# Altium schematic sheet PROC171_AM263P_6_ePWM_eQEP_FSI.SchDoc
size 431 x 279 mm; Date: Not shown in title block; ApprovedBy: Not shown in title block; CheckedBy: Not shown in title block; Author: Not shown in title block; CompanyName: Not shown in title block; Engineer: Not shown in title block; Organization: Not shown in title block; Address1: Not shown in title block; Address2: Not shown in title block; Address3: Not shown in title block; Address4: Not shown in title block; DocumentNumber: 10; Revision: Use project parameter SCH_Rev; SheetNumber: 10; SheetTotal: 26; PageSetup: Record=PageOptions¦CenterHorizontal=True¦CenterVertical=True¦PrintScale=1.00¦XCorrection=1.00¦YCorrection=1.00¦PrintKind=0¦BorderSize=5000000¦LeftOffset=0¦BottomOffset=0¦Orientation=2¦PaperLength=1000¦PaperWidth=1000¦Scale=100¦PaperSource=15¦PrintQuality=600¦MediaType=1¦DitherType=10¦PaperKind=Letter¦PrintScaleMode=1
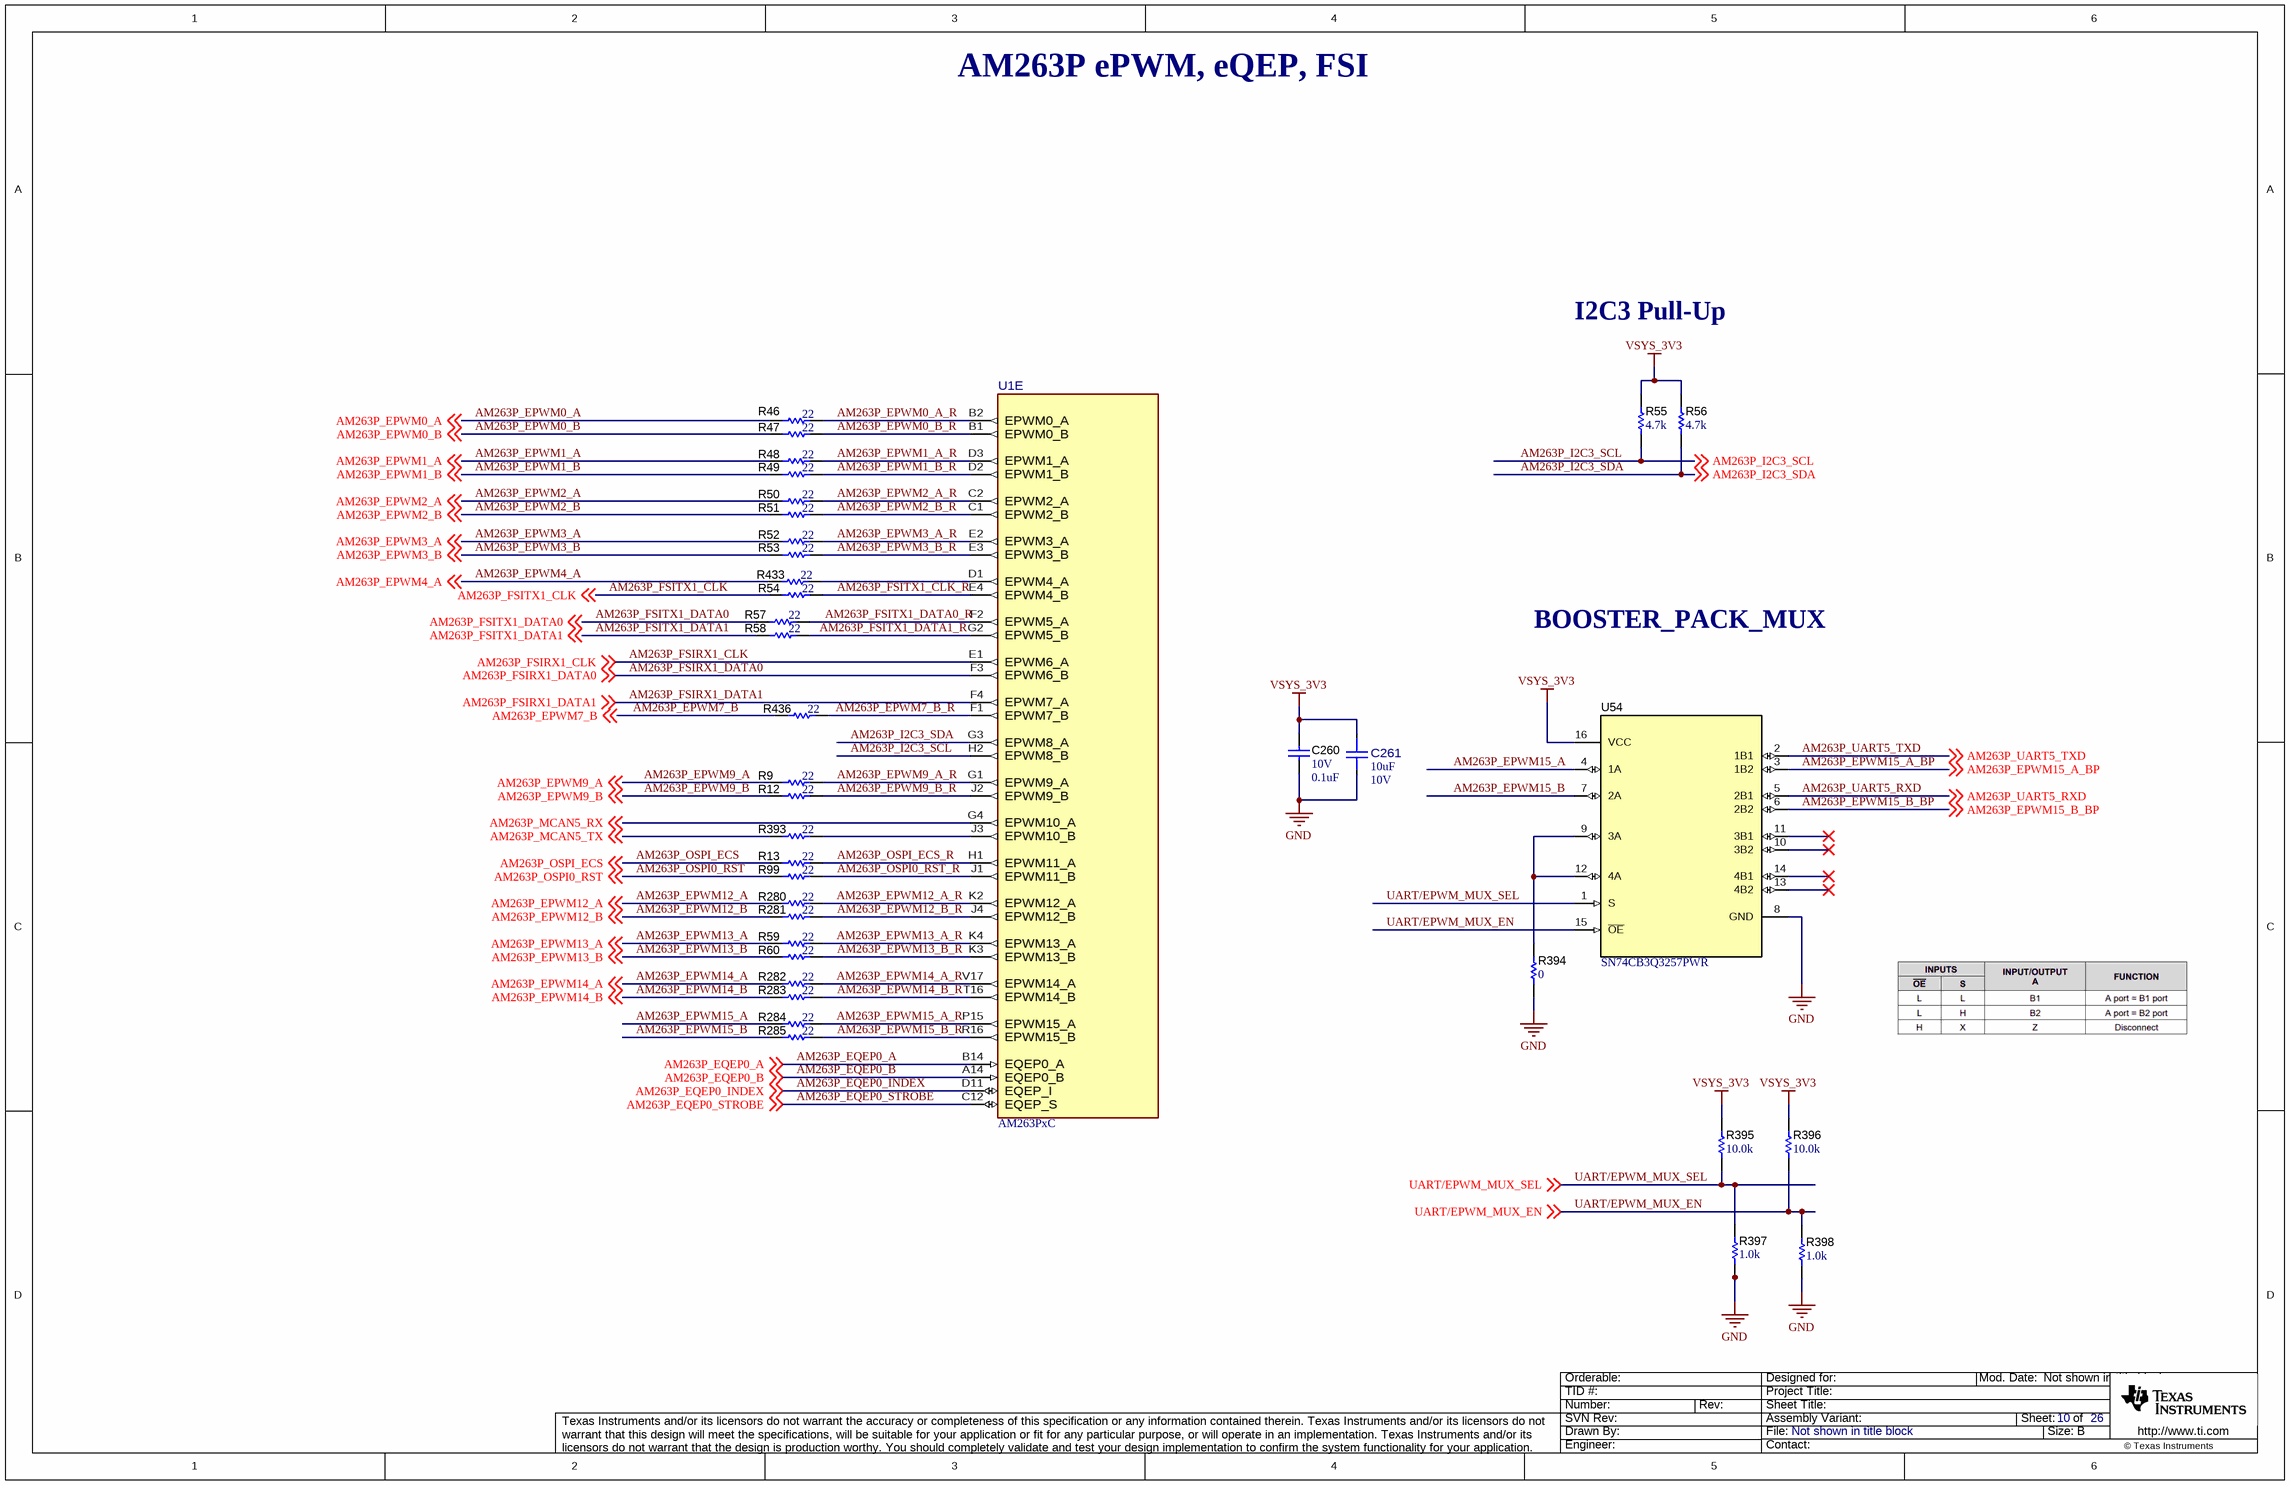
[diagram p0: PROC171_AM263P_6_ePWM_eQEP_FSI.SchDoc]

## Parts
C260  VDC_V: 10V  ValueDisplayed: 0.1uF  [0402]  (hidden comment: 885012105010)
C261  ValueDisplayed: 10uF  VDC_V: 10V  [FP-KGM05CR51A106MH_0402-MFG]  (hidden comment: KGM05CR51A106MH)
R9  ValueDisplayed: 22  [0402]  (hidden comment: CRCW040222R0JNED)
R12  ValueDisplayed: 22  [0402]  (hidden comment: CRCW040222R0JNED)
R13  ValueDisplayed: 22  [0402]  (hidden comment: CRCW040222R0JNED)
R46  ValueDisplayed: 22  [0402]  (hidden comment: CRCW040222R0JNED)
R47  ValueDisplayed: 22  [0402]  (hidden comment: CRCW040222R0JNED)
R48  ValueDisplayed: 22  [0402]  (hidden comment: CRCW040222R0JNED)
R49  ValueDisplayed: 22  [0402]  (hidden comment: CRCW040222R0JNED)
R50  ValueDisplayed: 22  [0402]  (hidden comment: CRCW040222R0JNED)
R51  ValueDisplayed: 22  [0402]  (hidden comment: CRCW040222R0JNED)
R52  ValueDisplayed: 22  [0402]  (hidden comment: CRCW040222R0JNED)
R53  ValueDisplayed: 22  [0402]  (hidden comment: CRCW040222R0JNED)
R54  ValueDisplayed: 22  [0402]  (hidden comment: CRCW040222R0JNED)
R55  ValueDisplayed: 4.7k  [0402]  (hidden comment: CRCW04024K70JNED)
R56  ValueDisplayed: 4.7k  [0402]  (hidden comment: CRCW04024K70JNED)
R57  ValueDisplayed: 22  [0402]  (hidden comment: CRCW040222R0JNED)
R58  ValueDisplayed: 22  [0402]  (hidden comment: CRCW040222R0JNED)
R59  ValueDisplayed: 22  [0402]  (hidden comment: CRCW040222R0JNED)
R60  ValueDisplayed: 22  [0402]  (hidden comment: CRCW040222R0JNED)
R99  ValueDisplayed: 22  [0402]  (hidden comment: CRCW040222R0JNED)
R280  ValueDisplayed: 22  [0402]  (hidden comment: CRCW040222R0JNED)
R281  ValueDisplayed: 22  [0402]  (hidden comment: CRCW040222R0JNED)
R282  ValueDisplayed: 22  [0402]  (hidden comment: CRCW040222R0JNED)
R283  ValueDisplayed: 22  [0402]  (hidden comment: CRCW040222R0JNED)
R284  ValueDisplayed: 22  [0402]  (hidden comment: CRCW040222R0JNED)
R285  ValueDisplayed: 22  [0402]  (hidden comment: CRCW040222R0JNED)
R393  ValueDisplayed: 22  [0402]  (hidden comment: CRCW040222R0JNED)
R394  value 0  [0402L]  (hidden comment: ERJ-2GE0R00X)
R395  ValueDisplayed: 10.0k  [0402]  (hidden comment: ERJ-2RKF1002X)
R396  ValueDisplayed: 10.0k  [0402]  (hidden comment: ERJ-2RKF1002X)
R397  ValueDisplayed: 1.0k  [0402]  (hidden comment: ERJ-2GEJ102X)
R398  ValueDisplayed: 1.0k  [0402]  (hidden comment: ERJ-2GEJ102X)
R433  ValueDisplayed: 22  [0402]  (hidden comment: CRCW040222R0JNED)
R436  ValueDisplayed: 22  [0402]  (hidden comment: CRCW040222R0JNED)
U1  AM263PxC  [ZCZ0324A-MFG]  (part E of 13)
U54  SN74CB3Q3257PWR  [PW0016A_L]

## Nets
GND: C260.2 C261.2 R394.1 R397.1 R398.1 U54.8(GND)
VSYS_3V3: C260.1 C261.1 R55.2 R56.2 R395.2 R396.2 U54.16(VCC)
AM263P_EPWM0_A: R46.1 ; off-sheet AM263P_EPWM0_A
AM263P_EPWM0_A_R: R46.2 U1.B2(EPWM0_A)
AM263P_EPWM0_B: R47.1 ; off-sheet AM263P_EPWM0_B
AM263P_EPWM0_B_R: R47.2 U1.B1(EPWM0_B)
AM263P_EPWM1_A: R48.1 ; off-sheet AM263P_EPWM1_A
AM263P_EPWM1_A_R: R48.2 U1.D3(EPWM1_A)
AM263P_EPWM1_B: R49.1 ; off-sheet AM263P_EPWM1_B
AM263P_EPWM1_B_R: R49.2 U1.D2(EPWM1_B)
AM263P_EPWM2_A: R50.1 ; off-sheet AM263P_EPWM2_A
AM263P_EPWM2_A_R: R50.2 U1.C2(EPWM2_A)
AM263P_EPWM2_B: R51.1 ; off-sheet AM263P_EPWM2_B
AM263P_EPWM2_B_R: R51.2 U1.C1(EPWM2_B)
AM263P_EPWM3_A: R52.1 ; off-sheet AM263P_EPWM3_A
AM263P_EPWM3_A_R: R52.2 U1.E2(EPWM3_A)
AM263P_EPWM3_B: R53.1 ; off-sheet AM263P_EPWM3_B
AM263P_EPWM3_B_R: R53.2 U1.E3(EPWM3_B)
AM263P_EPWM4_A: R433.1 ; off-sheet AM263P_EPWM4_A
AM263P_EPWM7_B: R436.1 ; off-sheet AM263P_EPWM7_B
AM263P_EPWM7_B_R: R436.2 U1.F1(EPWM7_B)
AM263P_EPWM9_A: R9.1 ; off-sheet AM263P_EPWM9_A
AM263P_EPWM9_A_R: R9.2 U1.G1(EPWM9_A)
AM263P_EPWM9_B: R12.1 ; off-sheet AM263P_EPWM9_B
AM263P_EPWM9_B_R: R12.2 U1.J2(EPWM9_B)
AM263P_EPWM12_A: R280.1 ; off-sheet AM263P_EPWM12_A
AM263P_EPWM12_A_R: R280.2 U1.K2(EPWM12_A)
AM263P_EPWM12_B: R281.1 ; off-sheet AM263P_EPWM12_B
AM263P_EPWM12_B_R: R281.2 U1.J4(EPWM12_B)
AM263P_EPWM13_A: R59.1 ; off-sheet AM263P_EPWM13_A
AM263P_EPWM13_A_R: R59.2 U1.K4(EPWM13_A)
AM263P_EPWM13_B: R60.1 ; off-sheet AM263P_EPWM13_B
AM263P_EPWM13_B_R: R60.2 U1.K3(EPWM13_B)
AM263P_EPWM14_A: R282.1 ; off-sheet AM263P_EPWM14_A
AM263P_EPWM14_A_R: R282.2 U1.V17(EPWM14_A)
AM263P_EPWM14_B: R283.1 ; off-sheet AM263P_EPWM14_B
AM263P_EPWM14_B_R: R283.2 U1.T16(EPWM14_B)
AM263P_EPWM15_A: R284.1 U54.4(1A)
AM263P_EPWM15_A_BP: U54.3(1B2) ; off-sheet AM263P_EPWM15_A_BP
AM263P_EPWM15_A_R: R284.2 U1.P15(EPWM15_A)
AM263P_EPWM15_B: R285.1 U54.7(2A)
AM263P_EPWM15_B_BP: U54.6(2B2) ; off-sheet AM263P_EPWM15_B_BP
AM263P_EPWM15_B_R: R285.2 U1.R16(EPWM15_B)
AM263P_EQEP0_A: U1.B14(EQEP0_A) ; off-sheet AM263P_EQEP0_A
AM263P_EQEP0_B: U1.A14(EQEP0_B) ; off-sheet AM263P_EQEP0_B
AM263P_EQEP0_INDEX: U1.D11(EQEP_I) ; off-sheet AM263P_EQEP0_INDEX
AM263P_EQEP0_STROBE: U1.C12(EQEP_S) ; off-sheet AM263P_EQEP0_STROBE
AM263P_FSIRX1_CLK: U1.E1(EPWM6_A) ; off-sheet AM263P_FSIRX1_CLK
AM263P_FSIRX1_DATA0: U1.F3(EPWM6_B) ; off-sheet AM263P_FSIRX1_DATA0
AM263P_FSIRX1_DATA1: U1.F4(EPWM7_A) ; off-sheet AM263P_FSIRX1_DATA1
AM263P_FSITX1_CLK: R54.1 ; off-sheet AM263P_FSITX1_CLK
AM263P_FSITX1_CLK_R: R54.2 U1.E4(EPWM4_B)
AM263P_FSITX1_DATA0: R57.1 ; off-sheet AM263P_FSITX1_DATA0
AM263P_FSITX1_DATA0_R: R57.2 U1.F2(EPWM5_A)
AM263P_FSITX1_DATA1: R58.1 ; off-sheet AM263P_FSITX1_DATA1
AM263P_FSITX1_DATA1_R: R58.2 U1.G2(EPWM5_B)
AM263P_I2C3_SCL: R55.1 U1.H2(EPWM8_B) ; off-sheet AM263P_I2C3_SCL
AM263P_I2C3_SDA: R56.1 U1.G3(EPWM8_A) ; off-sheet AM263P_I2C3_SDA
AM263P_MCAN5_RX: U1.G4(EPWM10_A) ; off-sheet AM263P_MCAN5_RX
AM263P_MCAN5_TX: R393.1 ; off-sheet AM263P_MCAN5_TX
AM263P_OSPI0_RST: R99.1 ; off-sheet AM263P_OSPI0_RST
AM263P_OSPI0_RST_R: R99.2 U1.J1(EPWM11_B)
AM263P_OSPI_ECS: R13.1 ; off-sheet AM263P_OSPI_ECS
AM263P_OSPI_ECS_R: R13.2 U1.H1(EPWM11_A)
AM263P_UART5_RXD: U54.5(2B1) ; off-sheet AM263P_UART5_RXD
AM263P_UART5_TXD: U54.2(1B1) ; off-sheet AM263P_UART5_TXD
UART/EPWM_MUX_EN: R396.1 R398.2 U54.15(~{OE}) ; off-sheet UART/EPWM_MUX_EN
UART/EPWM_MUX_SEL: R395.1 R397.2 U54.1(S) ; off-sheet UART/EPWM_MUX_SEL
NetR393_2: R393.2 U1.J3(EPWM10_B)
NetR394_2: R394.2 U54.9(3A) U54.12(4A)
NetR433_2: R433.2 U1.D1(EPWM4_A)

Not connected (* = marked no-connect by the designer): U54 10(3B2)* 11(3B1)* 13(4B2)* 14(4B1)*

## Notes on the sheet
- AM263P ePWM, eQEP, FSI
- I2C3 Pull-Up
- BOOSTER_PACK_MUX

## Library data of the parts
C260 = CMP-0006221-2: CAP, CERM, 0.1 uF, 10 V, +/- 20%, X5R, 0402; Manufacturer: Wurth Elektronik; TaMin_C: -55°C; Polarized: N; SizeAreaWB_mm2: 3; Value1: Unknown; U/M: EA; Value: 0.1uF; TaMax_C: 85°C; SizeZ_mm: 0.6; SizeX_mm: 1; SizeY_mm: 0.5; Cap_F: 100nF; AEC Category: Q200
C261 = CMP-0043010-1: 10 µF ±20% 10V Ceramic Capacitor X5R 0402 (1005 Metric); Manufacturer: KYOCERA AVX; AEC Qualified: No; Cap_F: 10µF; SizeZ_mm: 0.7mm; TempCo: 15%; Value: 10µF
R9 R12 R13 R46-R54 R57-R60 R99 R280-R285 R393 R433 R436 = CMP-0026880-3: RES, 22, 5%, 0.063 W, AEC-Q200 Grade 0, 0402; Manufacturer: Vishay-Dale; Power_W: 63mW; TempCo: 200 ppm/C; Value_Code: 22R0; Value: 22; EIA_Code: E24; SizeX_mm: 1; SizeY_mm: 0.5; SizeZ_mm: 0.6; Value2: 0.063W; AEC Qualified: Y; VDC_V: 50V; AEC Category: Q200; AEC Grade: 0
R55 R56 = CMP-0026938-5: RES, 4.7 k, 5%, 0.063 W, AEC-Q200 Grade 0, 0402; Manufacturer: Vishay-Dale; Power_W: 63mW; TempCo: 200 ppm/C; Value_Code: 4k70; Value: 4.7k; EIA_Code: E24; SizeX_mm: 1; SizeY_mm: 0.5; SizeZ_mm: 0.6; Value2: 0.063W; AEC Qualified: Y; VDC_V: 50V; AEC Category: Q200; AEC Grade: 0
R394 = CMP-0026992-3: RES, 0, 5%, 0.1 W, AEC-Q200 Grade 0, 0402; Manufacturer: Panasonic; Power_W: 100mW; TempCo: 600 ppm/C; Value_Code: 0000; EIA_Code: E24; SizeX_mm: 1; SizeY_mm: 0.5; SizeZ_mm: 0.6; Value2: 0.1W; AEC Qualified: Y; VDC_V: 50V; AEC Category: Q200; SizeAreaWB_mm2: 3
R395 R396 = CMP-0026658-1: RES, 10.0 k, 1%, 0.1 W, 0402; Manufacturer: Panasonic; Power_W: 100mW; TempCo: 100 ppm/C; Value_Code: 10k0; U/M: EA; Value: 10.0k; EIA_Code: E96; Res_ohm: 10k; SizeX_mm: 1; SizeY_mm: 0.5; SizeZ_mm: 0.6; Value2: 0.1W; VDC_V: 50V; AEC Category: Q200
R397 R398 = CMP-0078193-1: RES, 1.0 k, 5%, 0.1 W, AEC-Q200 Grade 0, 0402; Manufacturer: Panasonic; Value_Code: 1k00; SizeArea_mm2: 0.5; AEC Qualified: Y; AEC Category: Q200; Res_ohm: 1k; Value: 1.0k; SizeZ_mm: 0.6; Green_REACh: Passed; EIA_Code: E24; TempCo: 200 ppm/C; AEC Grade: 0; Power_W: 100mW; VDC_V: 50V; Value2: 0.1W; Green_Lifecycle: Active; U/M: EA; SizeX_mm: 1
U1 = CMP-0001698-2: Sitara™ Microcontroller; Manufacturer: Texas Instruments; SizeZ_mm: 1.4mm; Core Architecture: ARM Cortex-R5F; Data Bus Width: 32bits; Frequency_Fixed: 200MHz; Interface: I2C,SPI,UART,CAN,LIN,Ethernet,Other; Max Supply Voltage: 3.465V; Memory Size: 2MBytes; Memory Type: RAM; Min Supply Voltage: 1.14V; Number Of Cores: 1; Number Of I/Os: 140; Number Of I2C Channels: 4; Number Of Spi Channels: 5; Number Of Uart Channels: 6; Standoff Height: 0.35mm; AEC Category: Q200; CompType: IC
U54 = CMP-0076540-1: 4-Bit One-of-2 FET Multiplexer/Demultiplexer 2.5-V/3.3-V Low-Voltage, High-Bandwidth Bus Switch, PW0016A (TSSOP-16); Manufacturer: Texas Instruments; SizeAreaWB_mm2: 58.8; SizeArea_mm2: 32.0; SizeZ_mm: 1.2; SizeY_mm: 5.0; U/M: EA; CompType: IC; SizeX_mm: 6.4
